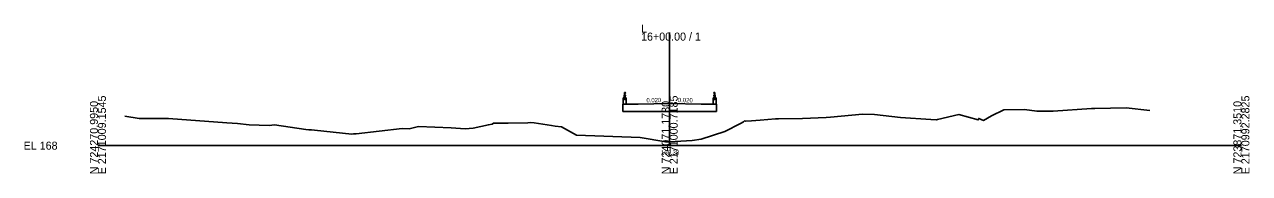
# Model space of a CAD drawing. Extents: x -26 to 2803, y -10 to 9553.
# Drawn here: x -25.7 to 402.8, y 7990.3 to 8042.3 of the extents above; entities that cross this region are included whole.
import ezdxf

# ---------------------------------------------------------------- set-up
doc = ezdxf.new("R2010")
doc.units = 0
for name, color, linetype in [('Exist Cross Section Cell', 7, 'Continuous'), ('Exist XS Center Line Elevation Label', 7, 'Continuous'), ('Exist XS Ground Line', 7, 'Continuous'), ('Prop XS Bridge', 7, 'Continuous'), ('Prop XS Dump Level', 7, 'Continuous'), ('Prop XS SE Text', 7, 'Continuous')]:
    doc.layers.add(name, color=color, linetype=linetype)

msp = doc.modelspace()

# ---------------------------------------------------------------- linework, layer by layer
at = {"layer": 'Exist Cross Section Cell'}
for p, q in [((200, 8000), (200, 8039.45)), ((0, 8000), (200, 8000)), ((200, 8000), (400, 8000))]:
    msp.add_line(p, q, dxfattribs=at)
at = {"layer": 'Exist XS Ground Line'}
msp.add_lwpolyline([(9.37, 8010.29), (14.45, 8009.5), (24.72, 8009.42), (45.1, 8008), (48.87, 8007.69), (52.93, 8007.3), (59.86, 8006.98), (61.82, 8007.25), (72.69, 8005.66), (73.81, 8005.52), (74.7, 8005.49), (75.78, 8005.42), (88.82, 8004.06), (89.39, 8004.08), (90.34, 8004.18), (106.4, 8005.99), (108.88, 8005.9), (112.19, 8006.67), (123.55, 8006.23), (128.43, 8005.83), (131.25, 8006.07), (136.57, 8007.32), (137.94, 8007.54), (138.38, 8007.82), (140.09, 8007.82), (143.48, 8007.81), (150.44, 8007.96), (151.33, 8008.07), (152.61, 8007.95), (158.66, 8007.05), (159.93, 8006.83), (162.21, 8006.55), (167.36, 8003.66), (189.66, 8002.83), (198.64, 8001.31), (200, 8001.38), (207.92, 8001.81), (211.01, 8002.32), (219.34, 8004.91), (224.8, 8007.69), (225.81, 8008.35), (226.23, 8008.62), (226.57, 8008.52), (228.61, 8008.61), (231.64, 8008.92), (237.07, 8009.37), (238.06, 8009.41), (246.43, 8009.49), (254.78, 8009.79), (256.3, 8009.9), (267.42, 8011.02), (271.68, 8010.89), (280.73, 8009.86), (291.36, 8009.18), (293.32, 8009.05), (293.72, 8009.13), (301.12, 8010.84), (307.95, 8008.97), (308.12, 8009.53), (309.82, 8008.83), (312.62, 8010.37), (316.95, 8012.53), (324.17, 8012.57), (328.44, 8012), (334.1, 8012.07), (347.59, 8012.98), (348.75, 8013.02), (359.72, 8013.15), (367.92, 8012.25)], dxfattribs=at)
at = {"layer": 'Prop XS Bridge'}
for p, q in [((184.19, 8018.51), (184.07, 8016.79)), ((184.19, 8018.51), (184.3, 8018.55)), ((184.19, 8016.76), (184.19, 8018.51)), ((184.37, 8018.55), (184.3, 8018.55)), ((184.3, 8016.76), (184.3, 8018.55)), ((184.37, 8016.76), (184.37, 8018.55)), ((184.43, 8018.52), (184.43, 8018.42)), ((184.43, 8018.32), (184.43, 8018.42)), ((215.57, 8018.52), (215.57, 8018.42)), ((215.57, 8018.32), (215.57, 8018.42)), ((215.63, 8018.55), (215.7, 8018.55)), ((215.63, 8016.76), (215.63, 8018.55)), ((215.81, 8018.51), (215.7, 8018.55)), ((215.7, 8016.76), (215.7, 8018.55)), ((215.81, 8016.76), (215.81, 8018.51)), ((215.81, 8018.51), (215.93, 8016.79)), ((183.57, 8014.4), (183.62, 8014.45)), ((183.57, 8014.4), (183.57, 8011.94)), ((183.7, 8014.45), (183.62, 8014.45)), ((183.69, 8016.67), (183.73, 8016.72)), ((183.69, 8016.67), (183.69, 8014.45)), ((184.75, 8014.45), (183.7, 8014.45)), ((184.7, 8016.72), (183.73, 8016.72)), ((184.07, 8016.81), (184.07, 8016.84)), ((184.07, 8016.76), (184.07, 8016.79)), ((184.2, 8016.69), (184.11, 8016.69)), ((184.2, 8016.68), (184.11, 8016.68)), ((184.15, 8016.64), (184.11, 8016.64)), ((184.15, 8016.63), (184.11, 8016.63)), ((184.15, 8016.6), (184.11, 8016.6)), ((184.15, 8016.59), (184.11, 8016.59)), ((184.15, 8016.56), (184.11, 8016.56)), ((184.15, 8016.55), (184.11, 8016.55)), ((184.15, 8016.52), (184.11, 8016.52)), ((184.15, 8016.51), (184.11, 8016.51)), ((184.15, 8016.67), (184.13, 8016.67)), ((184.15, 8016.65), (184.13, 8016.65)), ((184.15, 8016.62), (184.13, 8016.62)), ((184.15, 8016.61), (184.13, 8016.61)), ((184.15, 8016.58), (184.13, 8016.58)), ((184.15, 8016.57), (184.13, 8016.57)), ((184.15, 8016.54), (184.13, 8016.54)), ((184.15, 8016.53), (184.13, 8016.53)), ((184.18, 8016.83), (184.14, 8016.83)), ((184.14, 8016.83), (184.14, 8016.8)), ((184.14, 8016.68), (184.14, 8016.76)), ((184.16, 8016.67), (184.15, 8016.67)), ((184.15, 8016.67), (184.15, 8016.16)), ((184.18, 8016.67), (184.16, 8016.67)), ((184.16, 8016.67), (184.16, 8016.16)), ((184.18, 8016.65), (184.16, 8016.65)), ((184.2, 8016.64), (184.16, 8016.64)), ((184.2, 8016.63), (184.16, 8016.63)), ((184.18, 8016.62), (184.16, 8016.62)), ((184.18, 8016.61), (184.16, 8016.61)), ((184.2, 8016.6), (184.16, 8016.6)), ((184.2, 8016.59), (184.16, 8016.59)), ((184.18, 8016.58), (184.16, 8016.58)), ((184.18, 8016.57), (184.16, 8016.57)), ((184.2, 8016.56), (184.16, 8016.56)), ((184.2, 8016.55), (184.16, 8016.55)), ((184.18, 8016.54), (184.16, 8016.54)), ((184.18, 8016.53), (184.16, 8016.53)), ((184.2, 8016.52), (184.16, 8016.52)), ((184.2, 8016.51), (184.16, 8016.51)), ((184.18, 8016.8), (184.18, 8016.83)), ((184.18, 8016.68), (184.18, 8016.76)), ((184.19, 8017.69), (184.19, 8017.69)), ((184.43, 8016.11), (184.21, 8016.11)), ((184.43, 8016.1), (184.21, 8016.1)), ((184.43, 8017.58), (184.43, 8017.48)), ((184.43, 8017.38), (184.43, 8017.48)), ((184.53, 8016.69), (184.44, 8016.69)), ((184.53, 8016.68), (184.44, 8016.68)), ((184.48, 8016.64), (184.44, 8016.64)), ((184.48, 8016.63), (184.44, 8016.63)), ((184.48, 8016.6), (184.44, 8016.6)), ((184.48, 8016.59), (184.44, 8016.59)), ((184.48, 8016.56), (184.44, 8016.56)), ((184.48, 8016.55), (184.44, 8016.55)), ((184.48, 8016.52), (184.44, 8016.52)), ((184.48, 8016.51), (184.44, 8016.51)), ((184.48, 8016.67), (184.46, 8016.67)), ((184.48, 8016.65), (184.46, 8016.65)), ((184.48, 8016.62), (184.46, 8016.62)), ((184.48, 8016.61), (184.46, 8016.61)), ((184.48, 8016.58), (184.46, 8016.58)), ((184.48, 8016.57), (184.46, 8016.57)), ((184.48, 8016.54), (184.46, 8016.54)), ((184.48, 8016.53), (184.46, 8016.53)), ((184.51, 8016.84), (184.47, 8016.84)), ((184.47, 8016.84), (184.47, 8016.8)), ((184.47, 8016.69), (184.47, 8016.77)), ((184.49, 8016.67), (184.48, 8016.67)), ((184.48, 8016.67), (184.48, 8016.16)), ((184.51, 8016.67), (184.49, 8016.67)), ((184.49, 8016.67), (184.49, 8016.16)), ((184.51, 8016.65), (184.49, 8016.65)), ((184.53, 8016.64), (184.49, 8016.64)), ((184.53, 8016.63), (184.49, 8016.63)), ((184.51, 8016.62), (184.49, 8016.62)), ((184.51, 8016.61), (184.49, 8016.61)), ((184.53, 8016.6), (184.49, 8016.6)), ((184.53, 8016.59), (184.49, 8016.59)), ((184.51, 8016.58), (184.49, 8016.58)), ((184.51, 8016.57), (184.49, 8016.57)), ((184.53, 8016.56), (184.49, 8016.56)), ((184.53, 8016.55), (184.49, 8016.55)), ((184.51, 8016.54), (184.49, 8016.54)), ((184.51, 8016.53), (184.49, 8016.53)), ((184.53, 8016.52), (184.49, 8016.52)), ((184.53, 8016.51), (184.49, 8016.51)), ((184.51, 8016.8), (184.51, 8016.84)), ((184.51, 8016.69), (184.51, 8016.77)), ((184.7, 8016.72), (184.75, 8016.67)), ((184.75, 8016.67), (184.75, 8014.45)), ((189, 8014.53), (184.75, 8014.45)), ((189, 8014.53), (200, 8014.75)), ((200, 8014.75), (211, 8014.53)), ((211, 8014.53), (215.25, 8014.45)), ((215.25, 8016.67), (215.3, 8016.72)), ((215.25, 8016.67), (215.25, 8014.45)), ((215.25, 8014.45), (216.3, 8014.45)), ((215.3, 8016.72), (216.27, 8016.72)), ((215.47, 8016.69), (215.56, 8016.69)), ((215.47, 8016.68), (215.56, 8016.68)), ((215.47, 8016.64), (215.51, 8016.64)), ((215.47, 8016.63), (215.51, 8016.63)), ((215.47, 8016.6), (215.51, 8016.6)), ((215.47, 8016.59), (215.51, 8016.59)), ((215.47, 8016.56), (215.51, 8016.56)), ((215.47, 8016.55), (215.51, 8016.55)), ((215.47, 8016.52), (215.51, 8016.52)), ((215.47, 8016.51), (215.51, 8016.51)), ((215.49, 8016.8), (215.49, 8016.84)), ((215.49, 8016.84), (215.53, 8016.84)), ((215.49, 8016.69), (215.49, 8016.77)), ((215.49, 8016.67), (215.51, 8016.67)), ((215.49, 8016.65), (215.51, 8016.65)), ((215.49, 8016.62), (215.51, 8016.62)), ((215.49, 8016.61), (215.51, 8016.61)), ((215.49, 8016.58), (215.51, 8016.58)), ((215.49, 8016.57), (215.51, 8016.57)), ((215.49, 8016.54), (215.51, 8016.54)), ((215.49, 8016.53), (215.51, 8016.53)), ((215.51, 8016.67), (215.52, 8016.67)), ((215.51, 8016.67), (215.51, 8016.16)), ((215.52, 8016.67), (215.54, 8016.67)), ((215.52, 8016.67), (215.52, 8016.16)), ((215.52, 8016.65), (215.54, 8016.65)), ((215.52, 8016.64), (215.56, 8016.64)), ((215.52, 8016.63), (215.56, 8016.63)), ((215.52, 8016.62), (215.54, 8016.62)), ((215.52, 8016.61), (215.54, 8016.61)), ((215.52, 8016.6), (215.56, 8016.6)), ((215.52, 8016.59), (215.56, 8016.59)), ((215.52, 8016.58), (215.54, 8016.58)), ((215.52, 8016.57), (215.54, 8016.57)), ((215.52, 8016.56), (215.56, 8016.56)), ((215.52, 8016.55), (215.56, 8016.55)), ((215.52, 8016.54), (215.54, 8016.54)), ((215.52, 8016.53), (215.54, 8016.53)), ((215.52, 8016.52), (215.56, 8016.52)), ((215.52, 8016.51), (215.56, 8016.51)), ((215.53, 8016.84), (215.53, 8016.8)), ((215.53, 8016.69), (215.53, 8016.77)), ((215.57, 8017.58), (215.57, 8017.48)), ((215.57, 8017.38), (215.57, 8017.48)), ((215.57, 8016.11), (215.79, 8016.11)), ((215.57, 8016.1), (215.79, 8016.1)), ((215.8, 8016.69), (215.89, 8016.69)), ((215.8, 8016.68), (215.89, 8016.68)), ((215.8, 8016.64), (215.84, 8016.64)), ((215.8, 8016.63), (215.84, 8016.63)), ((215.8, 8016.6), (215.84, 8016.6)), ((215.8, 8016.59), (215.84, 8016.59)), ((215.8, 8016.56), (215.84, 8016.56)), ((215.8, 8016.55), (215.84, 8016.55)), ((215.8, 8016.52), (215.84, 8016.52)), ((215.8, 8016.51), (215.84, 8016.51)), ((215.81, 8017.69), (215.81, 8017.69)), ((215.82, 8016.8), (215.82, 8016.83)), ((215.82, 8016.83), (215.86, 8016.83)), ((215.82, 8016.68), (215.82, 8016.76)), ((215.82, 8016.67), (215.84, 8016.67)), ((215.82, 8016.65), (215.84, 8016.65)), ((215.82, 8016.62), (215.84, 8016.62)), ((215.82, 8016.61), (215.84, 8016.61)), ((215.82, 8016.58), (215.84, 8016.58)), ((215.82, 8016.57), (215.84, 8016.57)), ((215.82, 8016.54), (215.84, 8016.54)), ((215.82, 8016.53), (215.84, 8016.53)), ((215.84, 8016.67), (215.85, 8016.67)), ((215.84, 8016.67), (215.84, 8016.16)), ((215.85, 8016.67), (215.87, 8016.67)), ((215.85, 8016.67), (215.85, 8016.16)), ((215.85, 8016.65), (215.87, 8016.65)), ((215.85, 8016.64), (215.89, 8016.64)), ((215.85, 8016.63), (215.89, 8016.63)), ((215.85, 8016.62), (215.87, 8016.62)), ((215.85, 8016.61), (215.87, 8016.61)), ((215.85, 8016.6), (215.89, 8016.6)), ((215.85, 8016.59), (215.89, 8016.59)), ((215.85, 8016.58), (215.87, 8016.58)), ((215.85, 8016.57), (215.87, 8016.57)), ((215.85, 8016.56), (215.89, 8016.56)), ((215.85, 8016.55), (215.89, 8016.55)), ((215.85, 8016.54), (215.87, 8016.54)), ((215.85, 8016.53), (215.87, 8016.53)), ((215.85, 8016.52), (215.89, 8016.52)), ((215.85, 8016.51), (215.89, 8016.51)), ((215.86, 8016.83), (215.86, 8016.8)), ((215.86, 8016.68), (215.86, 8016.76)), ((215.93, 8016.81), (215.93, 8016.84)), ((215.93, 8016.76), (215.93, 8016.79)), ((216.27, 8016.72), (216.31, 8016.67)), ((216.3, 8014.45), (216.38, 8014.45)), ((216.31, 8016.67), (216.31, 8014.45)), ((216.43, 8014.4), (216.38, 8014.45)), ((216.43, 8014.4), (216.43, 8011.94)), ((216.43, 8011.94), (183.57, 8011.94))]:
    msp.add_line(p, q, dxfattribs=at)
for points in [[(184.37, 8018.3), (184.37, 8018.34), (184.39, 8018.34), (184.39, 8018.33), (184.39, 8018.33), (184.39, 8018.31), (184.42, 8018.31), (184.42, 8018.34), (184.42, 8018.42), (184.42, 8018.49), (184.42, 8018.52), (184.39, 8018.52), (184.39, 8018.5), (184.39, 8018.5), (184.39, 8018.5), (184.37, 8018.5), (184.37, 8018.54)], [(215.63, 8018.3), (215.63, 8018.34), (215.61, 8018.34), (215.61, 8018.33), (215.61, 8018.33), (215.61, 8018.31), (215.58, 8018.31), (215.58, 8018.34), (215.58, 8018.42), (215.58, 8018.49), (215.58, 8018.52), (215.61, 8018.52), (215.61, 8018.5), (215.61, 8018.5), (215.61, 8018.5), (215.63, 8018.5), (215.63, 8018.54)], [(184.55, 8016.72), (184.55, 8016.77), (184.39, 8016.77), (184.39, 8017.13), (184.37, 8017.13), (184.37, 8016.76), (184.07, 8016.76), (184.07, 8016.78), (184.07, 8016.78), (184.07, 8016.72), (184.21, 8016.72), (184.21, 8016.75), (184.35, 8016.75), (184.35, 8016.72), (184.55, 8016.72)], [(184.11, 8016.69), (184.11, 8016.68), (184.13, 8016.67), (184.13, 8016.65), (184.11, 8016.64), (184.11, 8016.63), (184.13, 8016.62), (184.13, 8016.61), (184.11, 8016.6), (184.11, 8016.59), (184.13, 8016.58), (184.13, 8016.57), (184.11, 8016.56), (184.11, 8016.55), (184.13, 8016.54), (184.13, 8016.53), (184.11, 8016.52), (184.11, 8016.51)], [(184.2, 8016.76), (184.2, 8016.76), (184.16, 8016.76), (184.12, 8016.76), (184.12, 8016.76)], [(184.19, 8016.76), (184.19, 8016.79), (184.18, 8016.8), (184.13, 8016.8), (184.13, 8016.79), (184.13, 8016.76), (184.19, 8016.76), (184.17, 8016.76), (184.17, 8016.79), (184.17, 8016.8), (184.17, 8016.79), (184.16, 8016.8), (184.15, 8016.8), (184.15, 8016.79), (184.15, 8016.76), (184.15, 8016.79), (184.14, 8016.8)], [(184.2, 8016.69), (184.2, 8016.68), (184.18, 8016.67), (184.18, 8016.65), (184.2, 8016.64), (184.2, 8016.63), (184.18, 8016.62), (184.18, 8016.61), (184.2, 8016.6), (184.2, 8016.59), (184.18, 8016.58), (184.18, 8016.57), (184.2, 8016.56), (184.2, 8016.55), (184.18, 8016.54), (184.18, 8016.53), (184.2, 8016.52), (184.2, 8016.51)], [(184.37, 8017.36), (184.37, 8017.4), (184.39, 8017.4), (184.39, 8017.4), (184.39, 8017.4), (184.39, 8017.38), (184.42, 8017.38), (184.42, 8017.41), (184.42, 8017.48), (184.42, 8017.56), (184.42, 8017.59), (184.39, 8017.59), (184.39, 8017.57), (184.39, 8017.57), (184.39, 8017.56), (184.37, 8017.56), (184.37, 8017.61)], [(184.44, 8016.69), (184.44, 8016.68), (184.46, 8016.67), (184.46, 8016.65), (184.44, 8016.64), (184.44, 8016.63), (184.46, 8016.62), (184.46, 8016.61), (184.44, 8016.6), (184.44, 8016.59), (184.46, 8016.58), (184.46, 8016.57), (184.44, 8016.56), (184.44, 8016.55), (184.46, 8016.54), (184.46, 8016.53), (184.44, 8016.52), (184.44, 8016.51)], [(184.53, 8016.77), (184.53, 8016.77), (184.49, 8016.77), (184.45, 8016.77), (184.45, 8016.77)], [(184.52, 8016.77), (184.52, 8016.8), (184.51, 8016.8), (184.46, 8016.8), (184.46, 8016.8), (184.46, 8016.77), (184.52, 8016.77), (184.5, 8016.77), (184.5, 8016.8), (184.5, 8016.8), (184.5, 8016.8), (184.49, 8016.8), (184.48, 8016.8), (184.48, 8016.8), (184.48, 8016.77), (184.48, 8016.8), (184.47, 8016.8)], [(184.53, 8016.69), (184.53, 8016.68), (184.51, 8016.67), (184.51, 8016.65), (184.53, 8016.64), (184.53, 8016.63), (184.51, 8016.62), (184.51, 8016.61), (184.53, 8016.6), (184.53, 8016.59), (184.51, 8016.58), (184.51, 8016.57), (184.53, 8016.56), (184.53, 8016.55), (184.51, 8016.54), (184.51, 8016.53), (184.53, 8016.52), (184.53, 8016.51)], [(215.45, 8016.72), (215.45, 8016.77), (215.61, 8016.77), (215.61, 8017.13), (215.63, 8017.13), (215.63, 8016.76), (215.93, 8016.76), (215.93, 8016.78), (215.93, 8016.78), (215.93, 8016.72), (215.79, 8016.72), (215.79, 8016.75), (215.65, 8016.75), (215.65, 8016.72), (215.45, 8016.72)], [(215.47, 8016.77), (215.47, 8016.77), (215.51, 8016.77), (215.55, 8016.77), (215.55, 8016.77)], [(215.47, 8016.69), (215.47, 8016.68), (215.49, 8016.67), (215.49, 8016.65), (215.47, 8016.64), (215.47, 8016.63), (215.49, 8016.62), (215.49, 8016.61), (215.47, 8016.6), (215.47, 8016.59), (215.49, 8016.58), (215.49, 8016.57), (215.47, 8016.56), (215.47, 8016.55), (215.49, 8016.54), (215.49, 8016.53), (215.47, 8016.52), (215.47, 8016.51)], [(215.48, 8016.77), (215.48, 8016.8), (215.49, 8016.8), (215.54, 8016.8), (215.54, 8016.8), (215.54, 8016.77), (215.48, 8016.77), (215.5, 8016.77), (215.5, 8016.8), (215.5, 8016.8), (215.5, 8016.8), (215.51, 8016.8), (215.52, 8016.8), (215.52, 8016.8), (215.52, 8016.77), (215.52, 8016.8), (215.53, 8016.8)], [(215.56, 8016.69), (215.56, 8016.68), (215.54, 8016.67), (215.54, 8016.65), (215.56, 8016.64), (215.56, 8016.63), (215.54, 8016.62), (215.54, 8016.61), (215.56, 8016.6), (215.56, 8016.59), (215.54, 8016.58), (215.54, 8016.57), (215.56, 8016.56), (215.56, 8016.55), (215.54, 8016.54), (215.54, 8016.53), (215.56, 8016.52), (215.56, 8016.51)], [(215.63, 8017.36), (215.63, 8017.4), (215.61, 8017.4), (215.61, 8017.4), (215.61, 8017.4), (215.61, 8017.38), (215.58, 8017.38), (215.58, 8017.41), (215.58, 8017.48), (215.58, 8017.56), (215.58, 8017.59), (215.61, 8017.59), (215.61, 8017.57), (215.61, 8017.57), (215.61, 8017.56), (215.63, 8017.56), (215.63, 8017.61)], [(215.8, 8016.76), (215.8, 8016.76), (215.84, 8016.76), (215.88, 8016.76), (215.88, 8016.76)], [(215.8, 8016.69), (215.8, 8016.68), (215.82, 8016.67), (215.82, 8016.65), (215.8, 8016.64), (215.8, 8016.63), (215.82, 8016.62), (215.82, 8016.61), (215.8, 8016.6), (215.8, 8016.59), (215.82, 8016.58), (215.82, 8016.57), (215.8, 8016.56), (215.8, 8016.55), (215.82, 8016.54), (215.82, 8016.53), (215.8, 8016.52), (215.8, 8016.51)], [(215.81, 8016.76), (215.81, 8016.79), (215.82, 8016.8), (215.87, 8016.8), (215.87, 8016.79), (215.87, 8016.76), (215.81, 8016.76), (215.83, 8016.76), (215.83, 8016.79), (215.83, 8016.8), (215.83, 8016.79), (215.84, 8016.8), (215.85, 8016.8), (215.85, 8016.79), (215.85, 8016.76), (215.85, 8016.79), (215.86, 8016.8)], [(215.89, 8016.69), (215.89, 8016.68), (215.87, 8016.67), (215.87, 8016.65), (215.89, 8016.64), (215.89, 8016.63), (215.87, 8016.62), (215.87, 8016.61), (215.89, 8016.6), (215.89, 8016.59), (215.87, 8016.58), (215.87, 8016.57), (215.89, 8016.56), (215.89, 8016.55), (215.87, 8016.54), (215.87, 8016.53), (215.89, 8016.52), (215.89, 8016.51)]]:
    msp.add_lwpolyline(points, dxfattribs=at)
for centre in [(184.12, 8016.53), (184.53, 8016.53), (215.47, 8016.53), (215.88, 8016.53)]:
    msp.add_circle(centre, 0.00793, dxfattribs=at)
for centre, radius, start, end in [((184.44, 8018.52), 0.00744, 90, 180), ((184.44, 8018.32), 0.00744, 180, 270), ((215.56, 8018.52), 0.00744, 0, 90), ((215.56, 8018.32), 0.00744, 270, 360), ((184.21, 8016.16), 0.0665, 180, 270), ((184.21, 8016.16), 0.0507, 180, 270), ((184.44, 8017.58), 0.00744, 90, 180), ((184.44, 8017.38), 0.00744, 180, 270), ((184.43, 8016.16), 0.0507, 270, 0), ((184.43, 8016.16), 0.0665, 270, 0), ((215.57, 8016.16), 0.0665, 180, 270), ((215.57, 8016.16), 0.0507, 180, 270), ((215.56, 8017.58), 0.00744, 0, 90), ((215.56, 8017.38), 0.00744, 270, 360), ((215.79, 8016.16), 0.0507, 270, 0), ((215.79, 8016.16), 0.0665, 270, 0)]:
    msp.add_arc(centre, radius, start, end, dxfattribs=at)
for centre, major_axis, ratio, start_param, end_param in [((184.37, 8018.42), (0.318, 0), 0.39036, 6.282787, 7.853967), ((184.37, 8018.42), (0.318, 0), 0.39036, 4.712404, 6.282787), ((184.44, 8018.42), (0.211, 0), 0.495501, 6.282718, 7.853881), ((184.44, 8018.42), (0.211, 0), 0.495501, 4.712489, 6.282718), ((215.63, 8018.42), (-0.318, 0), 0.39036, 4.712404, 6.283584), ((215.63, 8018.42), (-0.318, 0), 0.39036, 0.000398, 1.570782), ((215.56, 8018.42), (-0.211, 0), 0.495501, 4.712489, 6.283652), ((215.56, 8018.42), (-0.211, 0), 0.495501, 0.000467, 1.570696), ((184.37, 8017.48), (0.318, 0), 0.39036, 6.282787, 7.853967), ((184.37, 8017.48), (0.318, 0), 0.39036, 4.712404, 6.282787), ((184.44, 8017.48), (0.211, 0), 0.495501, 6.282718, 7.853881), ((184.44, 8017.48), (0.211, 0), 0.495501, 4.712489, 6.282718), ((215.63, 8017.48), (-0.318, 0), 0.39036, 4.712404, 6.283584), ((215.63, 8017.48), (-0.318, 0), 0.39036, 0.000398, 1.570782), ((215.56, 8017.48), (-0.211, 0), 0.495501, 4.712489, 6.283652), ((215.56, 8017.48), (-0.211, 0), 0.495501, 0.000467, 1.570696)]:
    msp.add_ellipse(centre, major_axis=major_axis, ratio=ratio, start_param=start_param, end_param=end_param, dxfattribs=at)
at = {"layer": 'Prop XS Dump Level'}
for p, q in [((189, 8014.53), (200, 8014.75)), ((200, 8014.75), (211, 8014.53))]:
    msp.add_line(p, q, dxfattribs=at)

# ---------------------------------------------------------------- texts
at = {"layer": 'Exist Cross Section Cell'}
for s, p in [('16+00.00 / 1', (190, 8036.65)), ('L', (190, 8039.45)), ('EL 168', (-26, 7998.6))]:
    msp.add_text(s, height=2.8, dxfattribs=at).set_placement(p)
for s, p in [('N 724270.9950', (0, 7990)), ('E 2171009.1545', (2.8, 7990)), ('N 724071.1730', (200, 7990)), ('E 2171000.7185', (202.8, 7990)), ('N 723871.3510', (400, 7990)), ('E 2170992.2825', (402.8, 7990))]:
    msp.add_text(s, height=2.8, rotation=90, dxfattribs=at).set_placement(p)
at = {"layer": 'Exist XS Center Line Elevation Label'}
msp.add_text('169.38', height=1.5, dxfattribs=at).set_placement((196.97, 7996.88))
at = {"layer": 'Prop XS SE Text'}
for rotation, p in [(1.1458, (191.88, 8015.09)), (358.8542, (202.88, 8015.19))]:
    msp.add_text('0.020', height=1.5, rotation=rotation, dxfattribs=at).set_placement(p)

doc.saveas('drawing.dxf')
